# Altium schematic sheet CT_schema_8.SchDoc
size 147 x 119 mm
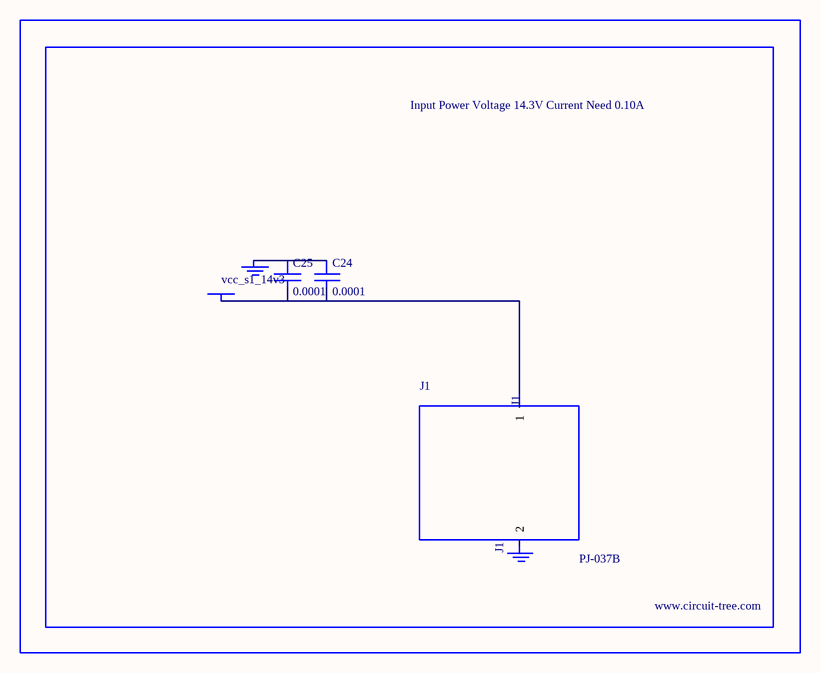
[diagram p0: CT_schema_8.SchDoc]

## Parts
BORDER7  (no value)
C24  0.0001  [EXV-9H]
C25  0.0001  [EXV-9H]
GND_INSTANCE_7_0  (no value)
GND_INSTANCE_7_1  (no value)
J1  PJ-037B  [PJ-037B_PACKAGE]
POWER_INSTANCE_7_0  vcc_s1_14v3

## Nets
NetC24_1: C24.1 C25.1 GND_INSTANCE_7_0.0(GND)
NetC24_2: C24.2 C25.2 J1.1 POWER_INSTANCE_7_0.0(PWR)

Not connected (* = marked no-connect by the designer): GND_INSTANCE_7_1 0(GND); J1 2

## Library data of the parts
BORDER7 = BORDER_PAGE7
C24 C25 = EDK107M035A9HAA
GND_INSTANCE_7_0 GND_INSTANCE_7_1 = GND
POWER_INSTANCE_7_0 = PWR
